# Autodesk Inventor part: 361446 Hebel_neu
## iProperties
Created: 2006-10
Part Number: 361446 Hebel_neu
Material: 1.0120.01
Description: Federlasche
Document SubType Name: Modeling
Designer: OSchmidt
Cost Center: 0,054 kg
Authority: 6914 mm^3
Density: 7.84 g/cm^3
Mass: 309.586 g
Surface Area: 152.75 cm^2
Volume: 39.488 cm^3
Abmessung: Fl. 40 x 4
HalbzeugNorm: DIN 174
Zweck: 266202
SaveDate: 2006-11-02
SaveTime: 21:02
TotalMass: 0,054 kg
TotalVolume: 6914 mm^3
Author: Schmidt
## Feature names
1. Extrusion2
2. Bohrung1 [Hole]
3. Rundung1 [Fillet]
